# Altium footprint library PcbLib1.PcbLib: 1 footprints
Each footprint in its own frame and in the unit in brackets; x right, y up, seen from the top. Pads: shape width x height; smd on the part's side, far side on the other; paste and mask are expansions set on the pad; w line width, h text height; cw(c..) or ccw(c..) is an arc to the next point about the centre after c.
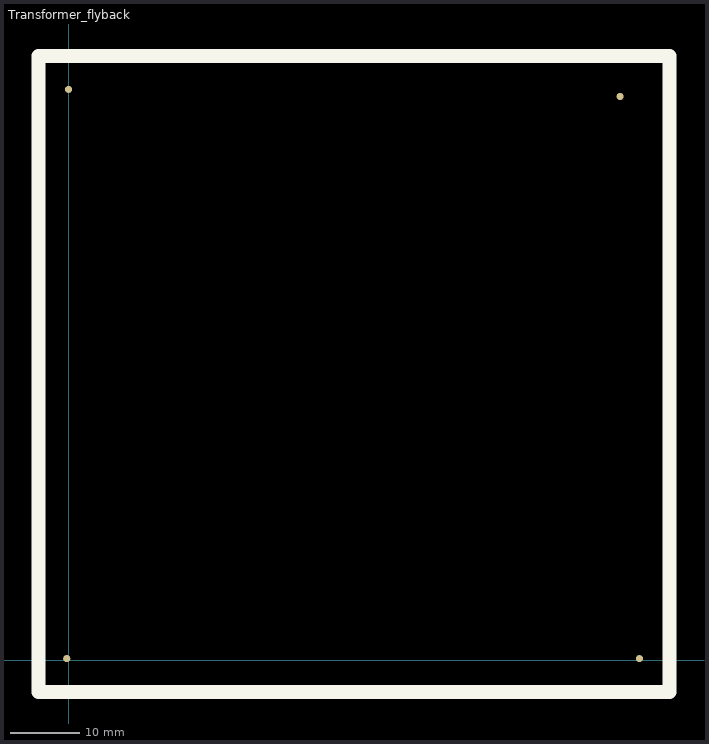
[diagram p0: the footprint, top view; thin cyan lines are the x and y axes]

## Transformer_flyback [mil]
pads (4):
  round 40 smd mask+100: 1(0,3230) 2(-10,10) 3(3120,3190) 4(3230,10)
Top Overlay:
  lines w78.74: -170,-180 -170,3420 3400,3420 3400,-180 -170,-180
